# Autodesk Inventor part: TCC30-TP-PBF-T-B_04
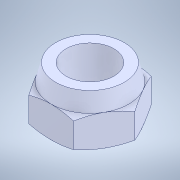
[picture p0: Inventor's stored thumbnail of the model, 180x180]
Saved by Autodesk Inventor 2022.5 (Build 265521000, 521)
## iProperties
Created: 2023-09
Part Number: TCC30-TP-PBF-T-B_04
Material: 一般
Document SubType Name: Modeling
Designer: ImaoCorp
Density: 1 g/cm^3
Appearance: 既定
Author: ImaoCorp
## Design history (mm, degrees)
feature "TCC30-TP-PBF-T-B_04"
node "ソリッド1"
